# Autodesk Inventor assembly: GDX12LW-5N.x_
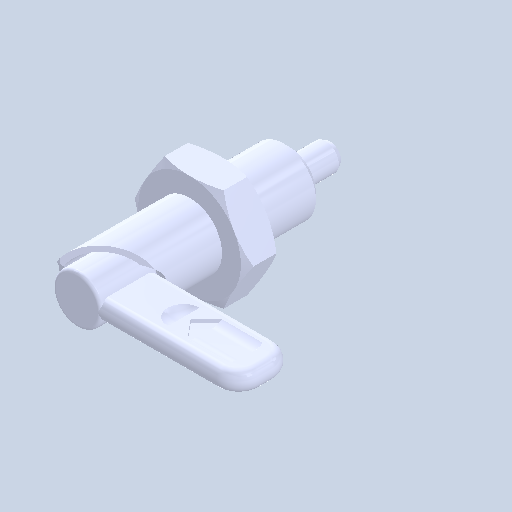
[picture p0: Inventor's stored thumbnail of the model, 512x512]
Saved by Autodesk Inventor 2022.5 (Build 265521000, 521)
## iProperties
Created: 2024-06
Part Number: GDX12LW-5N.x_
Document SubType Name: Assembly
Designer: ImaoCorp
Author: ImaoCorp
Sending System: SOLIDWORKS 2022-2022290
MC: AMD64
MC_MODEL: Intel64 Family 6 Model 60 Stepping 3, GenuineIntel
OS: Windows_NT
FRU: Parasolid Version 33.1, build 260,  4-25-2022
FORMAT: text
GUISE: transmit
KEY: FILEGDX12LW-5N.x_t
DATE: Wed Jun 12 09:31:55 2024
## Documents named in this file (4)
- Y:\5.更新分\2024年対応\xxxx_GDX\データ_imao品番\gdx12lw-5n\GDX12LW-5N.x_.iam
- Y:\5.更新分\2024年対応\xxxx_GDX\データ_imao品番\gdx12lw-5n\GDX12LW-5N_01.ipt
- Y:\5.更新分\2024年対応\xxxx_GDX\データ_imao品番\gdx12lw-5n\GDX12LW-5N_02.ipt
- Y:\5.更新分\2024年対応\xxxx_GDX\データ_imao品番\gdx12lw-5n\GDX12LW-5N_03.ipt
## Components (3 placed, 3 different names)
1. GDX12LW-5N_01
2. GDX12LW-5N_02
3. GDX12LW-5N_03
